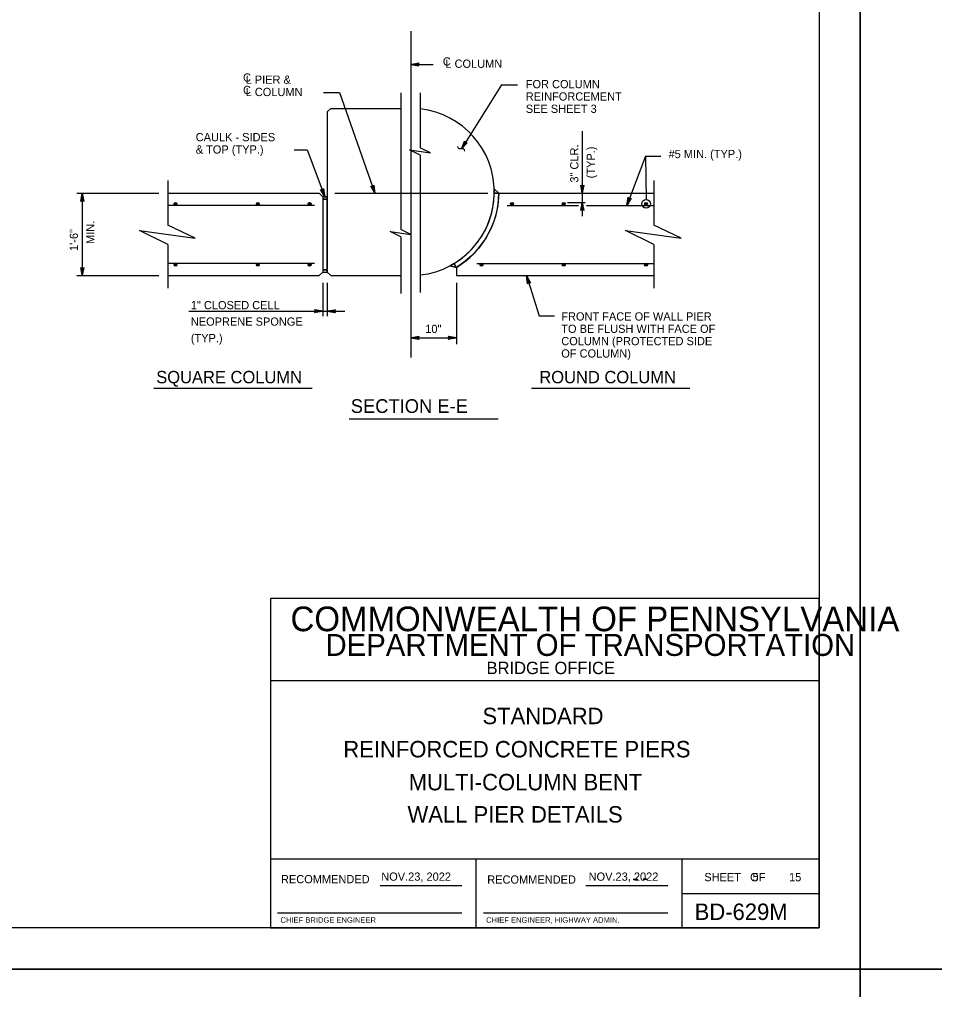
# Model space of a CAD drawing. Extents: x 646165 to 651486, y 296916 to 299292.
# Drawn here: x 649483 to 649816.7, y 298690.8 to 299044.4 of the extents above; entities that cross this region are included whole.
import ezdxf

# ---------------------------------------------------------------- set-up
doc = ezdxf.new("R2010")
doc.units = 0
for name, color, linetype in [('2', 7, 'Continuous'), ('50', 7, 'Continuous'), ('51', 7, 'Continuous'), ('52', 7, 'Continuous'), ('53', 7, 'Continuous'), ('54', 7, 'Continuous'), ('56', 7, 'Continuous'), ('60', 7, 'Continuous'), ('DATES', 7, 'Continuous'), ('PLT-BNDY', 7, 'Continuous'), ('SIGNATORY TITLES', 7, 'Continuous')]:
    doc.layers.add(name, color=color, linetype=linetype)

msp = doc.modelspace()

# ---------------------------------------------------------------- linework, layer by layer
at = {"layer": '2'}
for p, q in [((649774.59, 299277.25), (649774.59, 298713.25)), ((649774.59, 298833.25), (649574.59, 298833.25)), ((649574.59, 298833.25), (649574.59, 298713.25)), ((649774.59, 298713.25), (649774.59, 298833.25)), ((649774.59, 298803.25), (649574.59, 298803.25)), ((649774.59, 298738.25), (649574.59, 298738.25)), ((649649.59, 298713.25), (649649.59, 298738.25)), ((649724.59, 298738.25), (649724.59, 298713.25)), ((649614.56, 298728.75), (649644.32, 298728.75)), ((649689.56, 298728.75), (649719.46, 298728.75)), ((649724.59, 298725.75), (649774.59, 298725.75)), ((649577.09, 298718.75), (649644.32, 298718.75)), ((649652.22, 298718.75), (649719.46, 298718.75)), ((649774.59, 298713.25), (648988.59, 298713.25)), ((649574.59, 298713.25), (649774.59, 298713.25))]:
    msp.add_line(p, q, dxfattribs=at)
at = {"layer": '50'}
for p, q in [((649625.7, 299040.15), (649625.7, 298921.15)), ((649598, 298981.02), (649653.76, 298981.02))]:
    msp.add_line(p, q, dxfattribs=at)
at = {"layer": '51'}
for p, q in [((649595.24, 299010.69), (649596.5, 299011.95)), ((649595.24, 299010.69), (649595.24, 298952.29)), ((649596.5, 299011.95), (649622.13, 299011.95)), ((649537.09, 298981.02), (649592.3, 298981.02)), ((649592.3, 298981.02), (649593.57, 298979.75)), ((649657.83, 298981.02), (649656.14, 298982.69)), ((649657.83, 298981.02), (649656.16, 298981.04)), ((649657.83, 298981.02), (649714.31, 298981.02)), ((649593.57, 298979.75), (649593.57, 298952.29)), ((649593.57, 298979.75), (649595.24, 298979.75)), ((649593.57, 298978.89), (649595.24, 298978.89)), ((649642.37, 298954.01), (649641.5, 298955.44)), ((649592.3, 298951.02), (649593.57, 298952.29)), ((649593.57, 298953.15), (649595.24, 298953.15)), ((649593.57, 298952.29), (649595.24, 298952.29)), ((649595.24, 298952.29), (649596.5, 298951.02)), ((649642.37, 298954.01), (649640.05, 298954.61)), ((649642.37, 298954.01), (649642.37, 298951.02)), ((649537.09, 298951.02), (649592.3, 298951.02)), ((649596.5, 298951.02), (649622.13, 298951.02)), ((649642.37, 298951.02), (649714.31, 298951.02))]:
    msp.add_line(p, q, dxfattribs=at)
for radius, start, end in [(30.47, 276.7116, 83.2884), (32.13, 301.2432, 359.1678)]:
    msp.add_arc((649625.7, 298981.49), radius, start, end, dxfattribs=at)
at = {"layer": '52'}
for p, q in [((649625.7, 299027.97), (649633.84, 299027.97)), ((649658.77, 299020.52), (649644.15, 298997.21)), ((649658.77, 299020.52), (649664.66, 299020.52)), ((649593.83, 299017.78), (649599.71, 299017.78)), ((649599.71, 299017.78), (649612.63, 298981.02)), ((649622.04, 299017.57), (649622.04, 298967.8)), ((649629.14, 299017.57), (649629.14, 298997.55)), ((649688.25, 299003.6), (649688.25, 298972.73)), ((649583.14, 298996.91), (649587.94, 298996.91)), ((649587.94, 298996.91), (649594.39, 298979.75)), ((649629.14, 298994.91), (649629.14, 298944.79)), ((649711.28, 298994.49), (649704.48, 298976.62)), ((649711.28, 298994.49), (649716.86, 298994.49)), ((649711.28, 298994.49), (649711.47, 298978.75)), ((649537.09, 298985.62), (649537.09, 298969.38)), ((649714.31, 298985.62), (649714.31, 298969.38)), ((649503.9, 298981.02), (649533.83, 298981.02)), ((649505.91, 298981.02), (649505.91, 298951.02)), ((649682.88, 298977.69), (649689.25, 298977.69)), ((649711.49, 298977.15), (649711.49, 298977.15)), ((649622.04, 298965.16), (649622.04, 298944.52)), ((649537.09, 298962.35), (649537.09, 298946.39)), ((649714.31, 298962.35), (649714.31, 298946.39)), ((649503.9, 298951.02), (649533.83, 298951.02)), ((649593.57, 298948.39), (649593.57, 298936.22)), ((649595.24, 298948.39), (649595.24, 298936.22)), ((649642.37, 298948.39), (649642.37, 298926.04)), ((649667.94, 298951.02), (649672.47, 298936.36)), ((649544.76, 298938.02), (649601.65, 298938.02)), ((649672.47, 298936.36), (649678.08, 298936.36)), ((649625.7, 298928.31), (649642.37, 298928.31))]:
    msp.add_line(p, q, dxfattribs=at)
for points in [[(649625.7, 299027.97), (649628.68, 299028.53), (649628.57, 299028.45), (649628.45, 299028.37), (649628.39, 299028.27), (649628.33, 299028.17), (649628.32, 299028.07), (649628.3, 299027.97), (649628.32, 299027.87), (649628.33, 299027.77), (649628.39, 299027.67), (649628.45, 299027.57), (649628.57, 299027.49), (649628.68, 299027.41), (649625.7, 299027.97), (649628.57, 299027.49), (649628.45, 299027.57), (649625.7, 299027.97), (649628.39, 299027.67), (649628.33, 299027.77), (649625.7, 299027.97), (649628.32, 299027.87), (649628.3, 299027.97), (649625.7, 299027.97), (649628.32, 299028.07), (649628.33, 299028.17), (649625.7, 299027.97), (649628.39, 299028.27), (649628.45, 299028.37), (649625.7, 299027.97), (649628.57, 299028.45)], [(649644.15, 298997.21), (649645.26, 299000.03), (649645.27, 298999.89), (649645.27, 298999.75), (649645.33, 298999.65), (649645.38, 298999.55), (649645.46, 298999.48), (649645.53, 298999.41), (649645.62, 298999.37), (649645.72, 298999.34), (649645.83, 298999.33), (649645.95, 298999.33), (649646.08, 298999.38), (649646.21, 298999.44), (649644.15, 298997.21), (649646.08, 298999.38), (649645.95, 298999.33), (649644.15, 298997.21), (649645.83, 298999.33), (649645.72, 298999.34), (649644.15, 298997.21), (649645.62, 298999.37), (649645.53, 298999.41), (649644.15, 298997.21), (649645.46, 298999.48), (649645.38, 298999.55), (649644.15, 298997.21), (649645.33, 298999.65), (649645.27, 298999.75), (649644.15, 298997.21), (649645.27, 298999.89)], [(649629.14, 298994.91), (649625.25, 298996.81), (649632.86, 298995.78), (649629.14, 298997.55)], [(649612.63, 298981.02), (649611.11, 298983.65), (649611.34, 298983.48), (649611.57, 298983.44), (649611.77, 298983.47), (649611.94, 298983.57), (649612.09, 298983.75), (649612.17, 298984.02), (649612.63, 298981.02), (649612.09, 298983.75), (649611.94, 298983.57), (649612.63, 298981.02), (649611.77, 298983.47), (649611.57, 298983.44), (649612.63, 298981.02), (649611.34, 298983.48)], [(649688.25, 298981.02), (649687.69, 298984), (649687.85, 298983.77), (649688.05, 298983.65), (649688.25, 298983.62), (649688.45, 298983.65), (649688.65, 298983.77), (649688.81, 298984), (649688.25, 298981.02), (649688.65, 298983.77), (649688.45, 298983.65), (649688.25, 298981.02), (649688.25, 298983.62), (649688.05, 298983.65), (649688.25, 298981.02), (649687.85, 298983.77)], [(649505.91, 298981.02), (649506.47, 298978.04), (649506.31, 298978.27), (649506.11, 298978.39), (649505.91, 298978.42), (649505.71, 298978.39), (649505.51, 298978.27), (649505.35, 298978.04), (649505.91, 298981.02), (649505.51, 298978.27), (649505.71, 298978.39), (649505.91, 298981.02), (649505.91, 298978.42), (649506.11, 298978.39), (649505.91, 298981.02), (649506.31, 298978.27)], [(649594.39, 298979.75), (649592.82, 298982.35), (649593.05, 298982.19), (649593.28, 298982.15), (649593.48, 298982.19), (649593.65, 298982.29), (649593.8, 298982.47), (649593.87, 298982.74), (649594.39, 298979.75), (649593.8, 298982.47), (649593.65, 298982.29), (649594.39, 298979.75), (649593.48, 298982.19), (649593.28, 298982.15), (649594.39, 298979.75), (649593.05, 298982.19)], [(649688.25, 298977.69), (649688.81, 298974.7), (649688.65, 298974.93), (649688.45, 298975.05), (649688.25, 298975.09), (649688.05, 298975.05), (649687.85, 298974.93), (649687.69, 298974.7), (649688.25, 298977.69), (649687.85, 298974.93), (649688.05, 298975.05), (649688.25, 298977.69), (649688.25, 298975.09), (649688.45, 298975.05), (649688.25, 298977.69), (649688.65, 298974.93)], [(649704.48, 298976.62), (649705.02, 298979.61), (649705.08, 298979.33), (649705.23, 298979.15), (649705.4, 298979.05), (649705.6, 298979.01), (649705.83, 298979.05), (649706.06, 298979.21), (649704.48, 298976.62), (649705.83, 298979.05), (649705.6, 298979.01), (649704.48, 298976.62), (649705.4, 298979.05), (649705.23, 298979.15), (649704.48, 298976.62), (649705.08, 298979.33)], [(649537.09, 298962.35), (649526.72, 298967.42), (649547.01, 298964.66), (649537.09, 298969.38)], [(649622.04, 298965.16), (649618.15, 298967.06), (649625.76, 298966.03), (649622.04, 298967.8)], [(649714.31, 298962.35), (649703.94, 298967.42), (649724.24, 298964.66), (649714.31, 298969.38)], [(649505.91, 298951.02), (649505.35, 298954), (649505.51, 298953.77), (649505.71, 298953.65), (649505.91, 298953.62), (649506.11, 298953.65), (649506.31, 298953.77), (649506.47, 298954), (649505.91, 298951.02), (649506.31, 298953.77), (649506.11, 298953.65), (649505.91, 298951.02), (649505.91, 298953.62), (649505.71, 298953.65), (649505.91, 298951.02), (649505.51, 298953.77)], [(649667.94, 298951.02), (649669.36, 298948.34), (649669.25, 298948.42), (649669.14, 298948.51), (649669.02, 298948.53), (649668.91, 298948.56), (649668.81, 298948.55), (649668.71, 298948.54), (649668.62, 298948.49), (649668.53, 298948.44), (649668.45, 298948.36), (649668.37, 298948.27), (649668.33, 298948.14), (649668.29, 298948), (649667.94, 298951.02), (649668.33, 298948.14), (649668.37, 298948.27), (649667.94, 298951.02), (649668.45, 298948.36), (649668.53, 298948.44), (649667.94, 298951.02), (649668.62, 298948.49), (649668.71, 298948.54), (649667.94, 298951.02), (649668.81, 298948.55), (649668.91, 298948.56), (649667.94, 298951.02), (649669.02, 298948.53), (649669.14, 298948.51), (649667.94, 298951.02), (649669.25, 298948.42)], [(649593.57, 298938.02), (649590.58, 298937.46), (649590.7, 298937.54), (649590.81, 298937.62), (649590.87, 298937.72), (649590.93, 298937.82), (649590.95, 298937.92), (649590.97, 298938.02), (649590.95, 298938.12), (649590.93, 298938.22), (649590.87, 298938.32), (649590.81, 298938.42), (649590.7, 298938.5), (649590.58, 298938.58), (649593.57, 298938.02), (649590.7, 298938.5), (649590.81, 298938.42), (649593.57, 298938.02), (649590.87, 298938.32), (649590.93, 298938.22), (649593.57, 298938.02), (649590.95, 298938.12), (649590.97, 298938.02), (649593.57, 298938.02), (649590.95, 298937.92), (649590.93, 298937.82), (649593.57, 298938.02), (649590.87, 298937.72), (649590.81, 298937.62), (649593.57, 298938.02), (649590.7, 298937.54)], [(649595.24, 298938.02), (649598.22, 298938.58), (649598.1, 298938.5), (649597.99, 298938.42), (649597.93, 298938.32), (649597.87, 298938.22), (649597.85, 298938.12), (649597.84, 298938.02), (649597.85, 298937.92), (649597.87, 298937.82), (649597.93, 298937.72), (649597.99, 298937.62), (649598.1, 298937.54), (649598.22, 298937.46), (649595.24, 298938.02), (649598.1, 298937.54), (649597.99, 298937.62), (649595.24, 298938.02), (649597.93, 298937.72), (649597.87, 298937.82), (649595.24, 298938.02), (649597.85, 298937.92), (649597.84, 298938.02), (649595.24, 298938.02), (649597.85, 298938.12), (649597.87, 298938.22), (649595.24, 298938.02), (649597.93, 298938.32), (649597.99, 298938.42), (649595.24, 298938.02), (649598.1, 298938.5)], [(649625.7, 298928.31), (649628.68, 298928.87), (649628.57, 298928.79), (649628.45, 298928.71), (649628.39, 298928.61), (649628.33, 298928.51), (649628.32, 298928.41), (649628.3, 298928.31), (649628.32, 298928.21), (649628.33, 298928.11), (649628.39, 298928.01), (649628.45, 298927.91), (649628.57, 298927.83), (649628.68, 298927.75), (649625.7, 298928.31), (649628.57, 298927.83), (649628.45, 298927.91), (649625.7, 298928.31), (649628.39, 298928.01), (649628.33, 298928.11), (649625.7, 298928.31), (649628.32, 298928.21), (649628.3, 298928.31), (649625.7, 298928.31), (649628.32, 298928.41), (649628.33, 298928.51), (649625.7, 298928.31), (649628.39, 298928.61), (649628.45, 298928.71), (649625.7, 298928.31), (649628.57, 298928.79)], [(649642.37, 298928.31), (649639.38, 298927.75), (649639.5, 298927.83), (649639.61, 298927.91), (649639.67, 298928.01), (649639.73, 298928.11), (649639.75, 298928.21), (649639.77, 298928.31), (649639.75, 298928.41), (649639.73, 298928.51), (649639.67, 298928.61), (649639.61, 298928.71), (649639.5, 298928.79), (649639.38, 298928.87), (649642.37, 298928.31), (649639.5, 298928.79), (649639.61, 298928.71), (649642.37, 298928.31), (649639.67, 298928.61), (649639.73, 298928.51), (649642.37, 298928.31), (649639.75, 298928.41), (649639.77, 298928.31), (649642.37, 298928.31), (649639.75, 298928.21), (649639.73, 298928.11), (649642.37, 298928.31), (649639.67, 298928.01), (649639.61, 298927.91), (649642.37, 298928.31), (649639.5, 298927.83)]]:
    msp.add_lwpolyline(points, dxfattribs=at)
msp.add_circle((649711.49, 298977.15), 1.6, dxfattribs=at)
msp.add_spline([(649645.45, 298996.35), (649644.97, 298997.2), (649643.32, 298997.22), (649642.82, 298998.02)], degree=3, dxfattribs=at)
at = {"layer": '53'}
for p, q in [((649532.01, 298909.97), (649589.72, 298909.97)), ((649669.71, 298909.97), (649727.41, 298909.97)), ((649603.23, 298898.79), (649657.5, 298898.79))]:
    msp.add_line(p, q, dxfattribs=at)
at = {"layer": '54'}
for p, q in [((649590.57, 298976.62), (649537.09, 298976.62)), ((649660.83, 298976.62), (649686.85, 298976.62)), ((649689.83, 298976.62), (649714.31, 298976.62)), ((649590.57, 298955.42), (649537.09, 298955.42)), ((649649.75, 298955.42), (649714.31, 298955.42))]:
    msp.add_line(p, q, dxfattribs=at)
for centre, radius in [((649539.91, 298977.15), 0.533), ((649539.91, 298977.15), 0.4), ((649539.91, 298977.15), 0.267), ((649539.91, 298977.15), 0.133), ((649569.91, 298977.15), 0.533), ((649569.91, 298977.15), 0.4), ((649569.91, 298977.15), 0.267), ((649569.91, 298977.15), 0.133), ((649588.82, 298977.15), 0.533), ((649588.82, 298977.15), 0.4), ((649588.82, 298977.15), 0.267), ((649588.82, 298977.15), 0.133), ((649662.57, 298977.15), 0.533), ((649662.57, 298977.15), 0.4), ((649662.57, 298977.15), 0.267), ((649662.57, 298977.15), 0.133), ((649681.49, 298977.15), 0.533), ((649681.49, 298977.15), 0.4), ((649681.49, 298977.15), 0.267), ((649681.49, 298977.15), 0.133), ((649711.49, 298977.15), 0.533), ((649711.49, 298977.15), 0.4), ((649711.49, 298977.15), 0.267), ((649711.49, 298977.15), 0.133), ((649539.91, 298954.96), 0.533), ((649569.91, 298954.96), 0.533), ((649588.82, 298954.96), 0.533), ((649651.49, 298954.96), 0.533), ((649681.49, 298954.96), 0.533), ((649711.49, 298954.96), 0.533), ((649539.91, 298954.96), 0.4), ((649539.91, 298954.96), 0.267), ((649539.91, 298954.96), 0.133), ((649569.91, 298954.96), 0.4), ((649569.91, 298954.96), 0.267), ((649569.91, 298954.96), 0.133), ((649588.82, 298954.96), 0.4), ((649588.82, 298954.96), 0.267), ((649588.82, 298954.96), 0.133), ((649651.49, 298954.96), 0.4), ((649651.49, 298954.96), 0.267), ((649651.49, 298954.96), 0.133), ((649681.49, 298954.96), 0.4), ((649681.49, 298954.96), 0.267), ((649681.49, 298954.96), 0.133), ((649711.49, 298954.96), 0.4), ((649711.49, 298954.96), 0.267), ((649711.49, 298954.96), 0.133)]:
    msp.add_circle(centre, radius, dxfattribs=at)
at = {"layer": '56'}
for points in [[(649656.16, 298981.04), (649657.83, 298981.02), (649657.46, 298976.59), (649656.55, 298972.51), (649655.14, 298968.6), (649653.1, 298964.7), (649650.5, 298961.05), (649647.82, 298958.18), (649644.95, 298955.76), (649642.37, 298954.01), (649641.5, 298955.44), (649643.94, 298957.08), (649645.94, 298958.71), (649647.94, 298960.66), (649650.04, 298963.16), (649651.79, 298965.76), (649653.67, 298969.4), (649655.2, 298973.89), (649655.96, 298977.98)], [(649657.83, 298981.02), (649656.16, 298981.04), (649656.14, 298982.69)], [(649593.57, 298978.86), (649595.24, 298978.89), (649595.24, 298979.75), (649593.57, 298979.75)], [(649593.57, 298953.15), (649595.24, 298953.15), (649595.24, 298978.89), (649593.57, 298978.89)], [(649642.37, 298954.01), (649641.5, 298955.44), (649640.05, 298954.61)], [(649593.57, 298952.26), (649595.24, 298952.29), (649595.24, 298953.15), (649593.57, 298953.15)]]:
    msp.add_lwpolyline(points, close=True, dxfattribs=at)
at = {"layer": '60'}
for points in [[(649706.78, 298730.84), (649707.75, 298731.18), (649708.46, 298730.85)], [(649710.39, 298730.84), (649710.84, 298731.21), (649711.67, 298731.16), (649711.81, 298730.83), (649711.28, 298730.86)]]:
    msp.add_lwpolyline(points, close=True, dxfattribs=at)
at = {"layer": 'PLT-BNDY'}
for points in [[(648948.59, 299292.25), (649789.59, 299292.25), (649789.59, 298698.25), (648948.59, 298698.25)], [(649789.59, 299292.25), (650630.59, 299292.25), (650630.59, 298698.25), (649789.59, 298698.25)], [(648948.59, 298698.25), (649789.59, 298698.25), (649789.59, 298104.25), (648948.59, 298104.25)], [(649789.59, 298698.25), (650630.59, 298698.25), (650630.59, 298104.25), (649789.59, 298104.25)]]:
    msp.add_lwpolyline(points, close=True, dxfattribs=at)

# ---------------------------------------------------------------- texts
at = {"layer": '2'}
for s, height, p in [('COMMONWEALTH OF PENNSYLVANIA', 9, (649581.84, 298821.38)), ('DEPARTMENT OF TRANSPORTATION', 8.0003, (649594.59, 298812.38)), ('BRIDGE OFFICE', 4.5, (649653.34, 298805.75)), ('STANDARD', 6, (649651.84, 298787.5)), ('REINFORCED CONCRETE PIERS', 6, (649601.09, 298775.38)), ('MULTI-COLUMN BENT', 6, (649624.95, 298763.38)), ('WALL PIER DETAILS', 6, (649624.5, 298751.63)), ('SHEET   OF  ', 3, (649732.72, 298730.25)), ('5', 3, (649750.31, 298730.25)), ('15', 3, (649763.64, 298730.25)), ('BD-629M', 6, (649729.22, 298716.12))]:
    msp.add_text(s, height=height, dxfattribs=at).set_placement(p)
for p in [(649578.36, 298729.5), (649653.58, 298729.37)]:
    msp.add_text('RECOMMENDED', height=3, rotation=360, dxfattribs=at).set_placement(p)
at = {"layer": '53'}
for s, height, p in [('C', 3, (649637.38, 299027.56)), ('L COLUMN', 3, (649638.31, 299026.75)), ('C', 3, (649564.52, 299021.72)), ('L PIER &', 3, (649565.47, 299020.94)), ('C', 3, (649564.52, 299017.16)), ('L COLUMN', 3, (649565.47, 299016.44)), ('FOR COLUMN', 3, (649667.63, 299019.31)), ('REINFORCEMENT', 3, (649667.63, 299014.81)), ('SEE SHEET 3', 3, (649667.63, 299010.31)), ('CAULK - SIDES', 3, (649547.27, 298999.98)), ('& TOP (TYP.)', 3, (649547.27, 298995.48)), ('#5 MIN. (TYP.)', 3, (649719.69, 298993.83)), ('1" CLOSED CELL', 3, (649545.49, 298938.74)), ('NEOPRENE SPONGE', 3, (649545.49, 298932.74)), ('FRONT FACE OF WALL PIER', 3, (649680.57, 298934.63)), ('10"', 3, (649630.98, 298930.08)), ('TO BE FLUSH WITH FACE OF', 3, (649680.57, 298930.13)), ('(TYP.)', 3, (649545.49, 298926.74)), ('COLUMN (PROTECTED SIDE', 3, (649680.57, 298925.63)), ('OF COLUMN)', 3, (649680.57, 298921.13)), ('SQUARE COLUMN', 4.5, (649532.87, 298911.76)), ('ROUND COLUMN', 4.5, (649672.56, 298911.76)), ('SECTION E-E', 5, (649603.81, 298900.95))]:
    msp.add_text(s, height=height, dxfattribs=at).set_placement(p)
for s, p in [('3" CLR.', (649686.82, 298984.89)), ('(TYP.)', (649692.82, 298986.46)), ('MIN.', (649510.33, 298962.53)), ('1\'-6"', (649504.33, 298959.99))]:
    msp.add_text(s, height=3, rotation=90, dxfattribs=at).set_placement(p)
at = {"layer": 'DATES'}
for p in [(649614.93, 298730.43), (649690.55, 298730.43)]:
    msp.add_text('NOV.23, 2022', height=3, dxfattribs=at).set_placement(p)
at = {"layer": 'SIGNATORY TITLES'}
for s, p in [('CHIEF BRIDGE ENGINEER', (649578.18, 298715.12)), ('CHIEF ENGINEER, HIGHWAY ADMIN.', (649653.18, 298715.12))]:
    msp.add_text(s, height=2, dxfattribs=at).set_placement(p)

doc.saveas('drawing.dxf')
